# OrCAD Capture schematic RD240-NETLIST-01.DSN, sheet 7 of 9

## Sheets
7 3: size A3
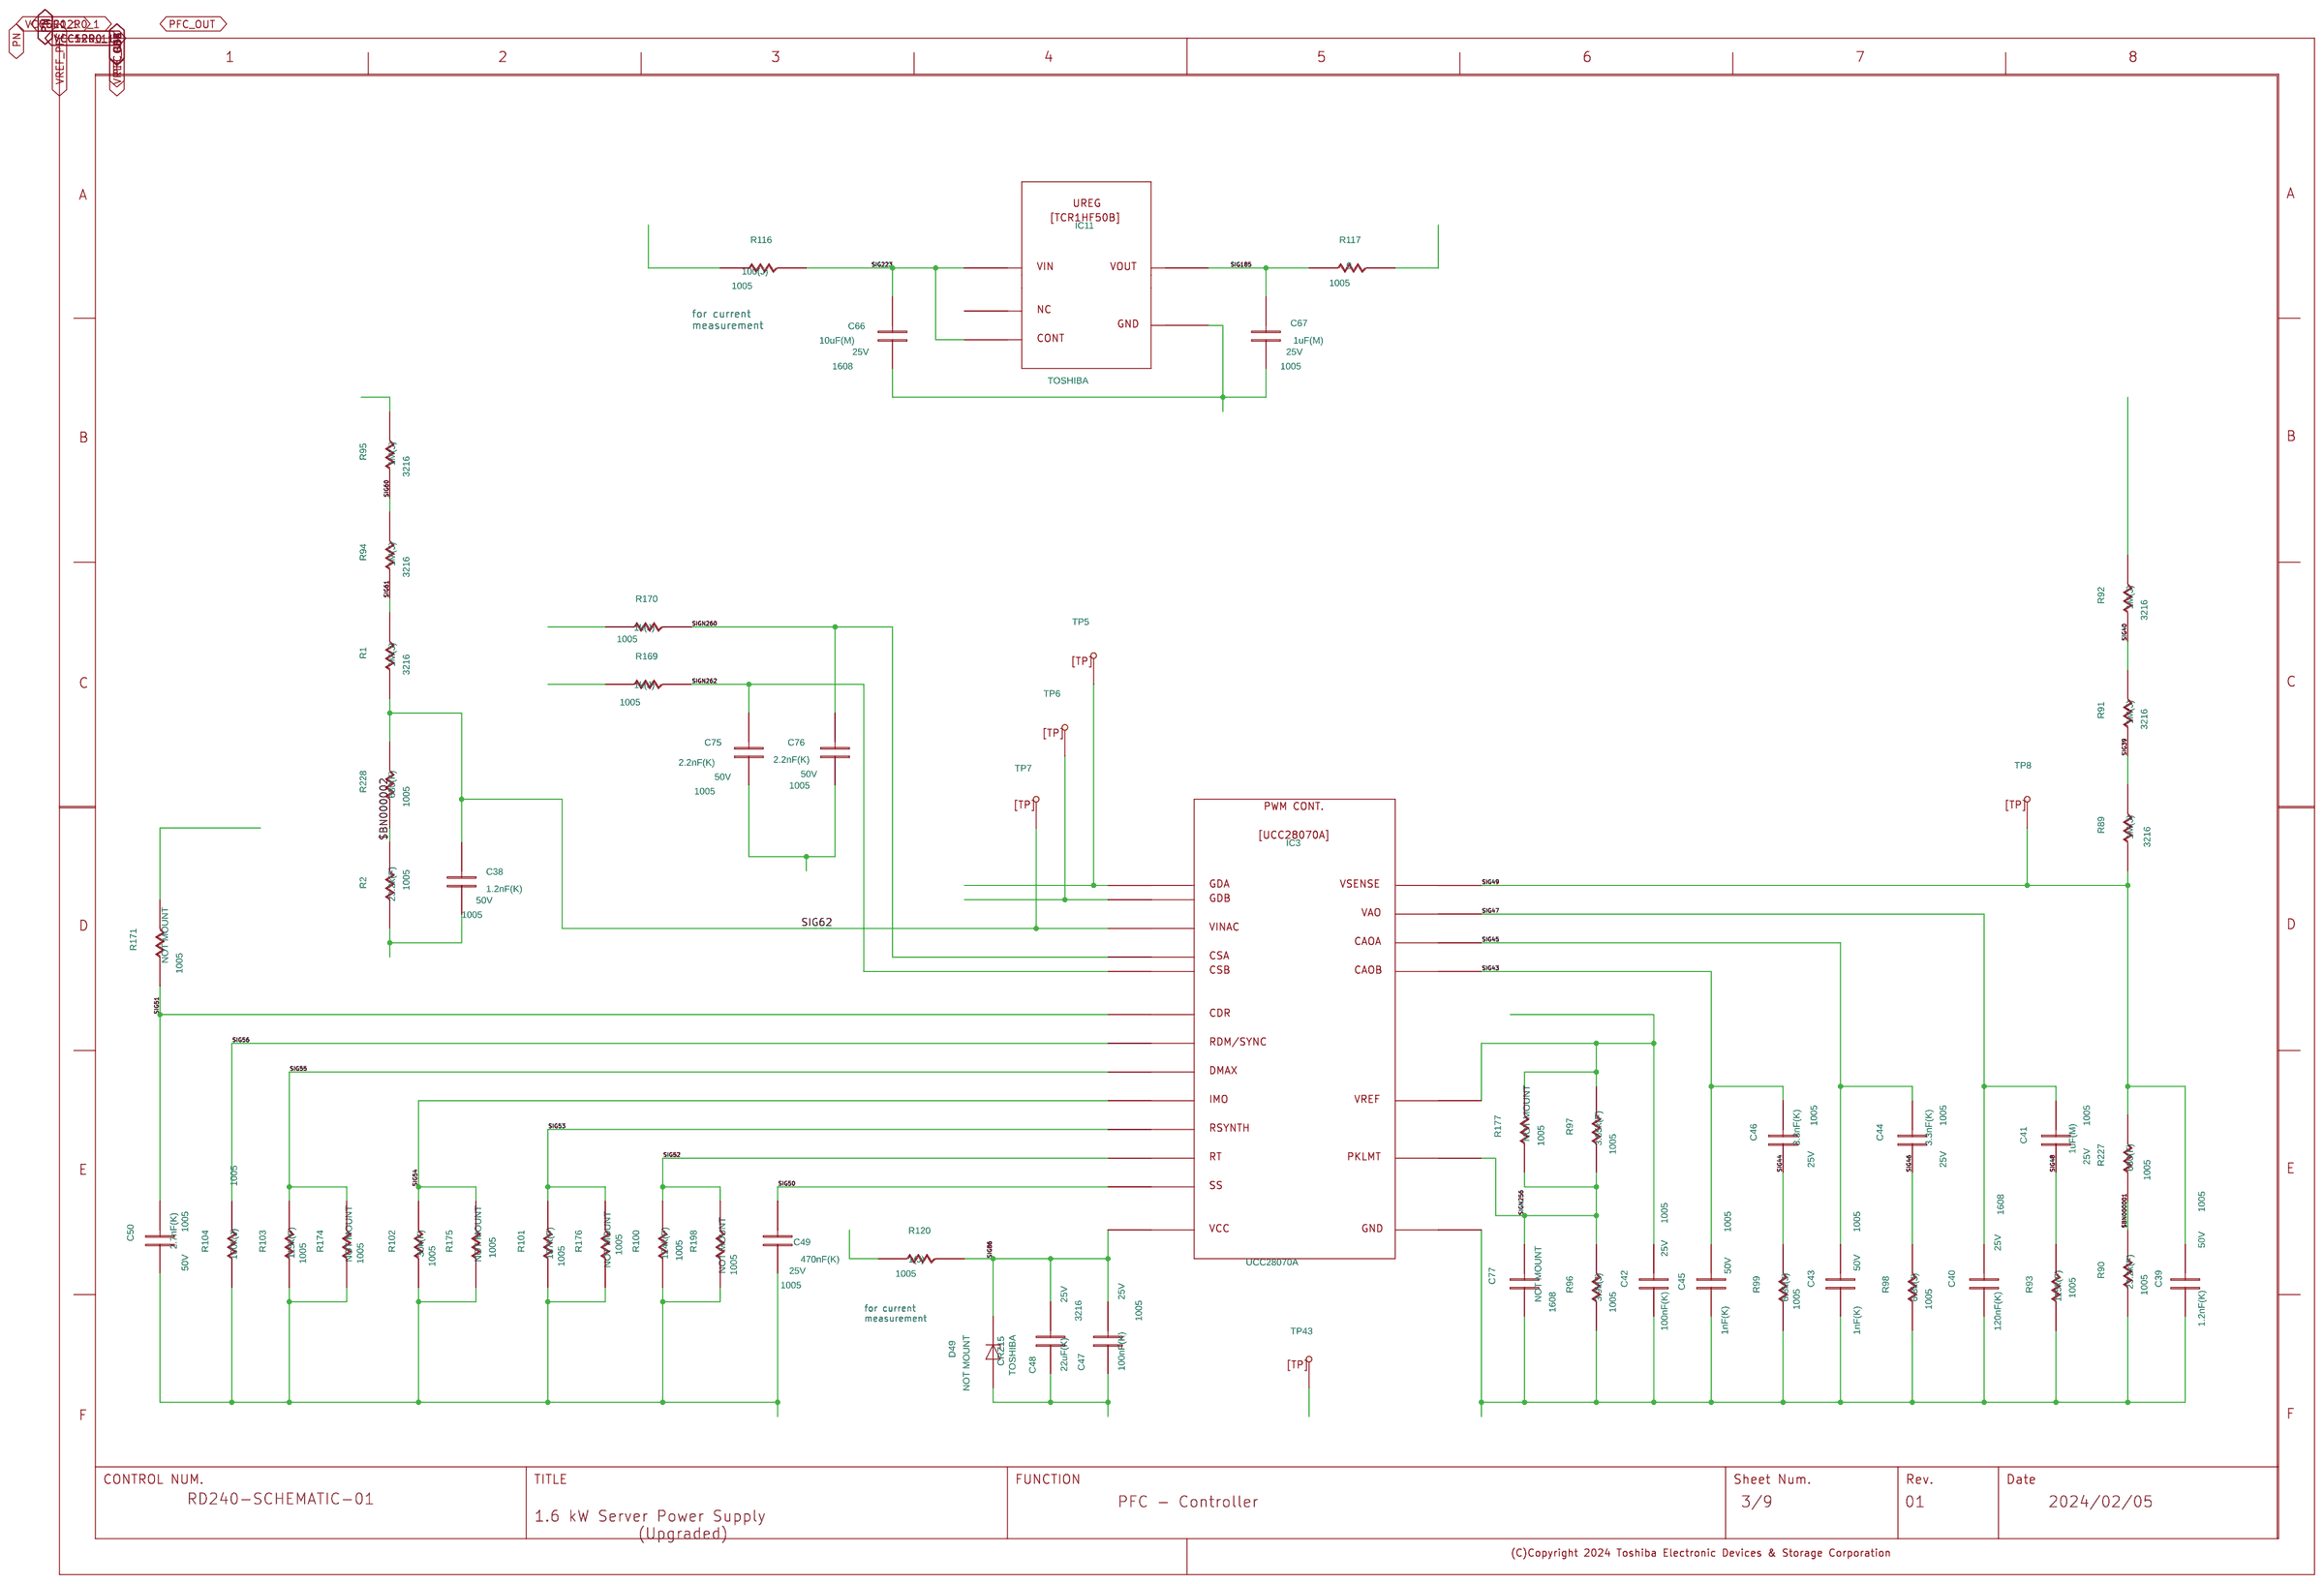
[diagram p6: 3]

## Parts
C38  C
C39  C
C40  C
C41  C
C42  C
C43  C
C44  C
C45  C
C46  C
C47  C
C48  C
C49  C
C50  C
C66  C
C67  C
C75  C
C76  C
C77  C
D49  ZD
IC3  L28070
IC11  TCR1HF50B
R1  R
R2  R
R89  R
R90  R
R91  R
R92  R
R93  R
R94  R
R95  R
R96  R
R97  R
R98  R
R99  R
R100  R
R101  R
R102  R
R103  R
R104  R
R116  R
R117  R
R120  R
R169  R
R170  R
R171  R
R174  R
R175  R
R176  R
R177  R
R198  R
R227  R
R228  R
TP5  TP
TP6  TP
TP7  TP
TP8  TP
TP43  TP
U?#6  WAKU_DEF100

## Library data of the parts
C38 = C: ADSMODELNAME: s_UMK105BJ122KV_F; AUTHOR: sptcae13; CAPACITANCETOLE: K; CDMASTERCADCELG: KC0005; CHIPSIZE: 1005; COMP: PRT_52; COMPONENTTYPE: 4; DATE: 2024/01/31; FNLEADFREETHET1GT2GMCTH1: 2_0_N; GCOUNT: 1; INSTANCENAME: cmp127; MAKER: TDK; MAXGCOUNT: 1; NOMINALCAPACITA: 1.2n; OUMECLASSIFICATION: ƒZƒ‰ƒ~ƒbƒNƒRƒ“ƒfƒ“ƒT; OUMEMAKER: TYD ‘¾—z—U“d; OUMEMAKERKATAMEI: UMK105BJ122KV-F; PMPRODUCTSTYPEG: HD1; QUADMODEL: CON_1.2N; RATEDVOLTAGE: 50; SAVECOUNT: 0; SIZECODESMD: 1005; TEMPCHARACTERI2: B; TIME: 13:58:26; UPDATEDATE: 2024/01/31; UPDATETIME: 13:58:26; UPDATEUSER: sptcae13; VAL1: 1.2nF(K); VAL2: 50V; VAL3: UMK105BJ122KV-F
C39 = C: ADSMODELNAME: s_UMK105BJ122KV_F; AUTHOR: sptcae13; CAPACITANCETOLE: K; CDMASTERCADCELG: KC0005; CHIPSIZE: 1005; COMP: PRT_52; COMPONENTTYPE: 4; DATE: 2024/01/31; FNLEADFREETHET1GT2GMCTH1: 2_0_N; GCOUNT: 1; INSTANCENAME: cmp128; MAKER: TDK; MAXGCOUNT: 1; NOMINALCAPACITA: 1.2n; OUMECLASSIFICATION: ƒZƒ‰ƒ~ƒbƒNƒRƒ“ƒfƒ“ƒT; OUMEMAKER: TYD ‘¾—z—U“d; OUMEMAKERKATAMEI: UMK105BJ122KV-F; PMPRODUCTSTYPEG: HD1; QUADMODEL: CON_1.2N; RATEDVOLTAGE: 50; SAVECOUNT: 0; SIZECODESMD: 1005; TEMPCHARACTERI2: B; TIME: 13:58:26; UPDATEDATE: 2024/01/31; UPDATETIME: 13:58:26; UPDATEUSER: sptcae13; VAL1: 1.2nF(K); VAL2: 50V; VAL3: UMK105BJ122KV-F
C40 = C: ADSMODELNAME: s_GCM188R71E154KA37D; AUTHOR: sptcae13; CAPACITANCETOLE: K; CDMASTERCADCELG: KC0008; CHIPSIZE: 1608; COMP: PRT_48; COMPONENTTYPE: 4; DATE: 2024/01/31; FNLEADFREETHET1GT2GMCTH1: N_N_N; GCOUNT: 1; INSTANCENAME: cmp76; MAKER: MURATA; MAXGCOUNT: 1; NOMINALCAPACITA: 150n; OUMECLASSIFICATION: ƒZƒ‰ƒ~ƒbƒNƒRƒ“ƒfƒ“ƒT; OUMEMAKER: MRT ºc»ì; OUMEMAKERKATAMEI: GCM188R71E154KA37D; PMPRODUCTSTYPEG: DME; QUADMODEL: CON_150N; RATEDVOLTAGE: 25; SAVECOUNT: 0; SIZECODESMD: 1608; TIME: 13:58:26; UPDATEDATE: 2024/01/31; UPDATETIME: 13:58:26; UPDATEUSER: sptcae13; VAL1: 120nF(K); VAL2: 25V; VAL3: GRM188R71E124KA01D
C41 = C: ADSMODELNAME: s_GCM31CR71H155KA55L; AUTHOR: sptcae13; CAPACITANCETOLE: K; CHIPSIZE: 2012; COMP: PRT_32; COMPONENTTYPE: 4; DATE: 2024/01/31; GCOUNT: 1; INSTANCENAME: cmp77; MAKER: TDK; MAXGCOUNT: 1; NOMINALCAPACITA: 1.5u; PMPRODUCTSTYPEG: DME; RATEDVOLTAGE: 50; SAVECOUNT: 0; SIZECODESMD: 1005; TIME: 13:58:26; UPDATEDATE: 2024/01/31; UPDATETIME: 13:58:26; UPDATEUSER: sptcae13; VAL1: 1uF(M); VAL2: 25V; VAL3: C1005X5R1E105M050BC
C42 = C: ADSMODELNAME: s_GRM155R71E104KE14D; AUTHOR: sptcae13; CAPACITANCETOLE: K; CDMASTERCADCELG: KC0005; CHIPSIZE: 1005; COMP: PRT_52; COMPONENTTYPE: 4; DATE: 2024/01/31; FNLEADFREETHET1GT2GMCTH1: N_N_N; GCOUNT: 1; INSTANCENAME: cmp62; MAKER: TDK; MAXGCOUNT: 1; NOMINALCAPACITA: 100n; OUMECLASSIFICATION: ƒZƒ‰ƒ~ƒbƒNƒRƒ“ƒfƒ“ƒT; OUMEMAKER: MRT ºc»ì; OUMEMAKERKATAMEI: GRM155R71E104KE14D; QUADMODEL: CON_100N; RATEDVOLTAGE: 25; SAVECOUNT: 0; SIZECODESMD: 1005; TIME: 13:58:26; UPDATEDATE: 2024/01/31; UPDATETIME: 13:58:26; UPDATEUSER: sptcae13; VAL1: 100nF(K); VAL2: 25V; VAL3: C1005X7R1E104K050BB
C43 = C: ADSMODELNAME: s_UMK105BJ102KV_F; AUTHOR: sptcae13; CAPACITANCETOLE: K; CDMASTERCADCELG: KC0005; CHIPSIZE: 1005; COMP: PRT_52; COMPONENTTYPE: 4; DATE: 2024/01/31; FNLEADFREETHET1GT2GMCTH1: 2_0_N; GCOUNT: 1; INSTANCENAME: cmp125; MAKER: TDK; MAXGCOUNT: 1; NOMINALCAPACITA: 1n; OUMECLASSIFICATION: ƒZƒ‰ƒ~ƒbƒNƒRƒ“ƒfƒ“ƒT; OUMEMAKER: TYD ‘¾—z—U“d; OUMEMAKERKATAMEI: UMK105BJ102KV-F; PMPRODUCTSTYPEG: HD1-PC1; QUADMODEL: CON_1N; RATEDVOLTAGE: 50; SAVECOUNT: 0; SIZECODESMD: 1005; TEMPCHARACTERI2: B; TIME: 13:58:26; UPDATEDATE: 2024/01/31; UPDATETIME: 13:58:26; UPDATEUSER: sptcae13; VAL1: 1nF(K); VAL2: 50V; VAL3: UMK105BJ102KV-F
C44 = C: ADSMODELNAME: s_C1005JB1E332KT; AUTHOR: sptcae13; CAPACITANCETOLE: K; CDMASTERCADCELG: KC0005; CHIPSIZE: 1005; COMP: PRT_52; COMPONENTTYPE: 4; DATE: 2024/01/31; FNLEADFREETHET1GT2GMCTH1: N_N_N; GCOUNT: 1; INSTANCENAME: cmp150; MAKER: TDK; MAXGCOUNT: 1; NOMINALCAPACITA: 3.3n; OUMECLASSIFICATION: ƒZƒ‰ƒ~ƒbƒNƒRƒ“ƒfƒ“ƒT; OUMEMAKER: TDK ‚s‚c‚j; OUMEMAKERKATAMEI: C1005JB1E332KT; QUADMODEL: CON_3.3N; RATEDVOLTAGE: 25; SAVECOUNT: 0; SIZECODESMD: 1005; TIME: 13:58:26; UPDATEDATE: 2024/01/31; UPDATETIME: 13:58:26; UPDATEUSER: sptcae13; VAL1: 3.3nF(K); VAL2: 25V; VAL3: CGJ2B2X7R1E332K050BA
C45 = C: ADSMODELNAME: s_UMK105BJ102KV_F; AUTHOR: sptcae13; CAPACITANCETOLE: K; CDMASTERCADCELG: KC0005; CHIPSIZE: 1005; COMP: PRT_52; COMPONENTTYPE: 4; DATE: 2024/01/31; FNLEADFREETHET1GT2GMCTH1: 2_0_N; GCOUNT: 1; INSTANCENAME: cmp126; MAKER: TDK; MAXGCOUNT: 1; NOMINALCAPACITA: 1n; OUMECLASSIFICATION: ƒZƒ‰ƒ~ƒbƒNƒRƒ“ƒfƒ“ƒT; OUMEMAKER: TYD ‘¾—z—U“d; OUMEMAKERKATAMEI: UMK105BJ102KV-F; PMPRODUCTSTYPEG: HD1-PC1; QUADMODEL: CON_1N; RATEDVOLTAGE: 50; SAVECOUNT: 0; SIZECODESMD: 1005; TEMPCHARACTERI2: B; TIME: 13:58:26; UPDATEDATE: 2024/01/31; UPDATETIME: 13:58:26; UPDATEUSER: sptcae13; VAL1: 1nF(K); VAL2: 50V; VAL3: UMK105BJ102KV-F
C46 = C: ADSMODELNAME: s_C1005JB1E332KT; AUTHOR: sptcae13; CAPACITANCETOLE: K; CDMASTERCADCELG: KC0005; CHIPSIZE: 1005; COMP: PRT_52; COMPONENTTYPE: 4; DATE: 2024/01/31; FNLEADFREETHET1GT2GMCTH1: N_N_N; GCOUNT: 1; INSTANCENAME: cmp149; MAKER: TDK; MAXGCOUNT: 1; NOMINALCAPACITA: 3.3n; OUMECLASSIFICATION: ƒZƒ‰ƒ~ƒbƒNƒRƒ“ƒfƒ“ƒT; OUMEMAKER: TDK ‚s‚c‚j; OUMEMAKERKATAMEI: C1005JB1E332KT; QUADMODEL: CON_3.3N; RATEDVOLTAGE: 25; SAVECOUNT: 0; SIZECODESMD: 1005; TIME: 13:58:26; UPDATEDATE: 2024/01/31; UPDATETIME: 13:58:26; UPDATEUSER: sptcae13; VAL1: 3.3nF(K); VAL2: 25V; VAL3: CGJ2B2X7R1E332K050BA
C47 = C: ADSCNVFLAG: ON; ADSCOMPONENTNAME: C_1005; ADSMODELNAME: s_GRM155R71E104KE14D; AUTHOR: sptcae13; CAPACITANCETOLE: K; CDMASTERCADCELG: KC0005; CHIPSIZE: 1005; COMP: PRT_52; COMPONENTTYPE: 4; DATE: 2024/01/31; FNLEADFREETHET1GT2GMCTH1: N_N_N; GCOUNT: 1; ICX_PART_MODEL: CON_100N; INSTANCENAME: cmp61; MAKER: TDK; MAXGCOUNT: 1; NOMINALCAPACITA: 100n; OUMECLASSIFICATION: ƒZƒ‰ƒ~ƒbƒNƒRƒ“ƒfƒ“ƒT; OUMEMAKER: MRT ºc»ì; OUMEMAKERKATAMEI: GRM155R71E104KE14D; QUADMODEL: CON_100N; RATEDVOLTAGE: 25; SAVECOUNT: 0; SIZECODESMD: 1005; SQ_PART_MODEL: CON_100N; TIME: 13:58:26; UPDATEDATE: 2024/01/31; UPDATETIME: 13:58:26; UPDATEUSER: sptcae13; VAL1: 100nF(K); VAL2: 25V; VAL3: C1005X7R1E104K050BB
C48 = C: ADSMODELNAME: s_GRM31CB31E226ME15D; AUTHOR: sptcae13; CAPACITANCETOLE: M; CDMASTERCADCELG: KC0014; CHIPSIZE: 3216; COMP: PRT_51; COMPONENTTYPE: 4; DATE: 2024/01/31; FNLEADFREETHET1GT2GMCTH1: N_N_N; GCOUNT: 1; INSTANCENAME: cmp147; MAKER: MURATA; MAXGCOUNT: 1; NOMINALCAPACITA: 22u; OUMECLASSIFICATION: ƒZƒ‰ƒ~ƒbƒNƒRƒ“ƒfƒ“ƒT; OUMEMAKER: MRT ºc»ì; OUMEMAKERKATAMEI: GRM31CB31E226ME15D; QUADMODEL: CON_22U; RATEDVOLTAGE: 25; SAVECOUNT: 0; SIZECODESMD: 3216; TEMPCHARACTERI2: B; TIME: 13:58:26; UPDATEDATE: 2024/01/31; UPDATETIME: 13:58:26; UPDATEUSER: sptcae13; VAL1: 22uF(K); VAL2: 25V; VAL3: GRM31CR61E226KE15L
C49 = C: ADSMODELNAME: s_GRM155R71E104KE14D; AUTHOR: sptcae13; CAPACITANCETOLE: K; CDMASTERCADCELG: KC0005; CHIPSIZE: 1005; COMP: PRT_52; COMPONENTTYPE: 4; DATE: 2024/01/31; FNLEADFREETHET1GT2GMCTH1: N_N_N; GCOUNT: 1; INSTANCENAME: cmp60; MAKER: TDK; MAXGCOUNT: 1; NOMINALCAPACITA: 100n; OUMECLASSIFICATION: ƒZƒ‰ƒ~ƒbƒNƒRƒ“ƒfƒ“ƒT; OUMEMAKER: MRT ºc»ì; OUMEMAKERKATAMEI: GRM155R71E104KE14D; QUADMODEL: CON_100N; RATEDVOLTAGE: 25; SAVECOUNT: 0; SIZECODESMD: 1005; TIME: 13:58:26; UPDATEDATE: 2024/01/31; UPDATETIME: 13:58:26; UPDATEUSER: sptcae13; VAL1: 470nF(K); VAL2: 25V; VAL3: C1005X5R1E474K050BB
C50 = C: ADSMODELNAME: s_UMK105BJ272KV_F; AUTHOR: sptcae13; CAPACITANCETOLE: K; CDMASTERCADCELG: DC834K; CHIPSIZE: 1005; COMP: PRT_52; COMPONENTTYPE: 4; DATE: 2024/01/31; FNLEADFREETHET1GT2GMCTH1: 3_0_N; GCOUNT: 1; INSTANCENAME: cmp131; MAKER: TDK; MAXGCOUNT: 1; NOMINALCAPACITA: 2.7n; OUMECLASSIFICATION: ƒZƒ‰ƒ~ƒbƒNƒRƒ“ƒfƒ“ƒT; OUMEMAKER: TYD ‘¾—z—U“d; OUMEMAKERKATAMEI: UMK105BJ272KV-F; PMPRODUCTSTYPEG: PC1; QUADMODEL: CON_2.7N; RATEDVOLTAGE: 50; SAVECOUNT: 0; SIZECODESMD: 1005; TEMPCHARACTERI2: B; TIME: 13:58:26; UPDATEDATE: 2024/01/31; UPDATETIME: 13:58:26; UPDATEUSER: sptcae13; VAL1: 2.7nF(K); VAL2: 50V; VAL3: UMK105BJ272KV-F
C66 = C: ADSMODELNAME: s_ZRB18AR61E106ME01L; AUTHOR: sptcae13; CAPACITANCETOLE: M; CDMASTERCADCELG: KC0167; CHIPSIZE: 1608; COMP: PRT_48; COMPONENTTYPE: 4; DATE: 2024/01/31; FNLEADFREETHET1GT2GMCTH1: N_N_N; GCOUNT: 1; INSTANCENAME: cmp160; MAKER: TDK; MAXGCOUNT: 1; NOMINALCAPACITA: 10u; OUMECLASSIFICATION: ƒZƒ‰ƒ~ƒbƒNƒRƒ“ƒfƒ“ƒT; OUMEMAKER: MRT ºc»ì; OUMEMAKERKATAMEI: ZRB18AR61E106ME01L; QUADMODEL: CON_10U; RATEDVOLTAGE: 25; SAVECOUNT: 0; SIZECODESMD: 1608; TIME: 13:58:26; UPDATEDATE: 2024/01/31; UPDATETIME: 13:58:26; UPDATEUSER: sptcae13; VAL1: 10uF(M); VAL2: 25V; VAL3: C1608X5R1E106M080AC
C67 = C: ADSCNVFLAG: ON; ADSCOMPONENTNAME: C_1608; ADSMODELNAME: s_GRM185B31E105KA12D; AUTHOR: sptcae13; CAPACITANCETOLE: K; CDMASTERCADCELG: KC0008; CHIPSIZE: 1005; COMP: PRT_52; COMPONENTTYPE: 4; DATE: 2024/01/31; FNLEADFREETHET1GT2GMCTH1: N_N_N; GCOUNT: 1; ICX_PART_MODEL: CON_1U; INSTANCENAME: cmp162; MAKER: TDK; MAXGCOUNT: 1; NOMINALCAPACITA: 1u; OUMECLASSIFICATION: ƒZƒ‰ƒ~ƒbƒNƒRƒ“ƒfƒ“ƒT; OUMEMAKER: MRT ºc»ì; OUMEMAKERKATAMEI: GRM185B31E105KA12D; PMPRODUCTSTYPEG: HD1; QUADMODEL: CON_1U; RATEDVOLTAGE: 25; SAVECOUNT: 0; SIZECODESMD: 1005; SQ_PART_MODEL: CON_1U; TEMPCHARACTERI2: B; TIME: 13:58:26; UPDATEDATE: 2024/01/31; UPDATETIME: 13:58:26; UPDATEUSER: sptcae13; VAL1: 1uF(M); VAL2: 25V; VAL3: C1005X5R1E105M050BC
C75 = C: ADSMODELNAME: s_UMK105BJ222KV_F; AUTHOR: sptcae13; CAPACITANCETOLE: K; CDMASTERCADCELG: KC0005; CHIPSIZE: 1005; COMP: PRT_52; COMPONENTTYPE: 4; DATE: 2024/01/31; FNLEADFREETHET1GT2GMCTH1: 2_0_N; GCOUNT: 1; INSTANCENAME: cmp129; MAKER: TDK; MAXGCOUNT: 1; NOMINALCAPACITA: 2.2n; OUMECLASSIFICATION: ƒZƒ‰ƒ~ƒbƒNƒRƒ“ƒfƒ“ƒT; OUMEMAKER: TYD ‘¾—z—U“d; OUMEMAKERKATAMEI: UMK105BJ222KV-F; PMPRODUCTSTYPEG: HD1-PC1; QUADMODEL: CON_2.2N; RATEDVOLTAGE: 50; SAVECOUNT: 0; SIZECODESMD: 1005; TEMPCHARACTERI2: B; TIME: 13:58:26; UPDATEDATE: 2024/01/31; UPDATETIME: 13:58:26; UPDATEUSER: sptcae13; VAL1: 2.2nF(K); VAL2: 50V; VAL3: UMK105BJ222KV-F
C76 = C: ADSMODELNAME: s_UMK105BJ222KV_F; AUTHOR: sptcae13; CAPACITANCETOLE: K; CDMASTERCADCELG: KC0005; CHIPSIZE: 1005; COMP: PRT_52; COMPONENTTYPE: 4; DATE: 2024/01/31; FNLEADFREETHET1GT2GMCTH1: 2_0_N; GCOUNT: 1; INSTANCENAME: cmp130; MAKER: TDK; MAXGCOUNT: 1; NOMINALCAPACITA: 2.2n; OLDCOMPONENTID: 99; OUMECLASSIFICATION: ƒZƒ‰ƒ~ƒbƒNƒRƒ“ƒfƒ“ƒT; OUMEMAKER: TYD ‘¾—z—U“d; OUMEMAKERKATAMEI: UMK105BJ222KV-F; PMPRODUCTSTYPEG: HD1-PC1; QUADMODEL: CON_2.2N; RATEDVOLTAGE: 50; SAVECOUNT: 0; SIZECODESMD: 1005; TEMPCHARACTERI2: B; TIME: 13:58:26; UPDATEDATE: 2024/01/31; UPDATETIME: 13:58:26; UPDATEUSER: sptcae13; VAL1: 2.2nF(K); VAL2: 50V; VAL3: UMK105BJ222KV-F
C77 = C: AUTHOR: sptcae13; CHIPSIZE: 1608; COMP: PRT_48; COMPONENTTYPE: 4; DATE: 2024/01/31; INSTANCENAME: cmp93; MAKER: MURATA; NOTMOUNT: NOT MOUNT; SAVECOUNT: 0; SIZECODESMD: 1608; TIME: 13:58:26; UPDATEDATE: 2024/01/31; UPDATETIME: 13:58:26; UPDATEUSER: sptcae13; VAL1: 100pF(J); VAL2: 50V; VAL3: GRM1885C1H101JA01D
D49 = ZD: ADSMODELNAME: s_CRZ15; CDMASTERCADCELG: MMK0167; COMPONENTTYPE: 4; FNLEADFREETHET1GT2GMCTH1: N_N_N; FORWARDVOLTAGEM: 0; GCOUNT: 1; INSTANCENAME: cmp51; MAXAVERAGEFORWA: 0; MAXGCOUNT: 1; MAXREPETITIVEPE: 0; MAXREVERSEVOLTA: 0; MOUNTINGFORMSMD: SMD; NOTMOUNT: NOT MOUNT; OUMECLASSIFICATION: èd³_CI[h; OUMEMAKER: TSB “ŒŽÅ; OUMEMAKERKATAMEI: CRZ15; OUMEPARTTYPE: D; PEAKFORWARDVOLT: 0; REVERSECURRENT: 0; USERCOMPTEXT3: TOSHIBA; VAL3: CRZ15; ZENERVOLTAGEMAX: 16.5; ZENERVOLTAGEMIN: 13.5
IC3 = L28070: COMP: PRT_59; COMPONENTTYPE: 4; INSTANCENAME: cmp10; MAKER: TEXAS; VAL3: UCC28070A
IC11 = TCR1HF50B: COMPONENTTYPE: 4; INSTANCENAME: cmp172; USERCOMPTEXT3: TOSHIBA
R1 = R: ADSMODELNAME: s_RK73H1JTTD1004F; CDMASTERCADCELG: KC0167; CHIPSIZE: 1608; COMPONENTTYPE: 4; FNLEADFREETHET1GT2GMCTH1: N_N_N; GCOUNT: 1; INSTANCENAME: cmp137; MAKER: KOA; MAXGCOUNT: 1; MOUNTINGFORMSMD: SMD; NOMINALRESISTAN: 1M; OUMECLASSIFICATION: \ÊÀpÅèïRí; OUMEMAKER: KOA R[A; OUMEMAKERKATAMEI: RK73H1JTTD1004F; POWERRATING: 100m; QUADMODEL: RES_1M; RESISTANCETOLER: F; SAVECOUNT: 0; SIZECODESMD: 3216; VAL1: 1M(J); VAL2: 250mW; VAL3: RK73B2BTTD105J
R2 = R: ADSMODELNAME: s_RC0402FR_071KL; ALLGREEN: 0:O[; CDMASTERCADCELG: KC0005; CHIPSIZE: 1608; COMPONENTTYPE: 4; FNAPPROVALRESUG: B:i(GREEN); FNCANCELLATIONG: 0:Žg—p‰Â; FNENVIRONMANTRG: 1:gpL(K§ÎÛO); FNLEADFREETHET1GT2GMCTH1: 2_2_N; GANSWERREV: 8; GCOUNT: 1; INSTANCENAME: cmp138; MAKER: PANASONIC; MAXGCOUNT: 1; MOUNTINGFORMSMD: SMD; NOMINALRESISTAN: 1K; OUMECLASSIFICATION: \ÊÀpÅèïRí; OUMEMAKER: YGO ƒ„ƒQƒI; OUMEMAKERKATAMEI: RC0402FR-071KL; PMPRODUCTSTYPEG: HD1; POWERRATING: 63m; QUADMODEL: RES_1K; RESISTANCETOLER: F; SAVECOUNT: 0; SIZECODESMD: 1005; VAL1: 23.2k(F); VAL2: 63mW; VAL3: ERJ2RKF2322X
R89 = R: ADSMODELNAME: s_RK73H1JTTD1004F; CDMASTERCADCELG: KC0167; CHIPSIZE: 1608; COMPONENTTYPE: 4; FNLEADFREETHET1GT2GMCTH1: N_N_N; GCOUNT: 1; INSTANCENAME: cmp142; MAKER: KOA; MAXGCOUNT: 1; MOUNTINGFORMSMD: SMD; NOMINALRESISTAN: 1M; OUMECLASSIFICATION: \ÊÀpÅèïRí; OUMEMAKER: KOA R[A; OUMEMAKERKATAMEI: RK73H1JTTD1004F; POWERRATING: 100m; QUADMODEL: RES_1M; RESISTANCETOLER: F; SAVECOUNT: 0; SIZECODESMD: 3216; VAL1: 1M(J); VAL2: 250mW; VAL3: RK73B2BTTD105J
R90 = R: ADSMODELNAME: s_RC0402FR_071KL; ALLGREEN: 0:O[; CDMASTERCADCELG: KC0005; CHIPSIZE: 1608; COMPONENTTYPE: 4; FNAPPROVALRESUG: B:i(GREEN); FNCANCELLATIONG: 0:Žg—p‰Â; FNENVIRONMANTRG: 1:gpL(K§ÎÛO); FNLEADFREETHET1GT2GMCTH1: 2_2_N; GANSWERREV: 8; GCOUNT: 1; INSTANCENAME: cmp153; MAKER: PANASONIC; MAXGCOUNT: 1; MOUNTINGFORMSMD: SMD; NOMINALRESISTAN: 1K; OUMECLASSIFICATION: \ÊÀpÅèïRí; OUMEMAKER: YGO ƒ„ƒQƒI; OUMEMAKERKATAMEI: RC0402FR-071KL; PMPRODUCTSTYPEG: HD1; POWERRATING: 63m; QUADMODEL: RES_1K; RESISTANCETOLER: F; SAVECOUNT: 0; SIZECODESMD: 1005; VAL1: 23.2k(F); VAL2: 63mW; VAL3: ERJ2RKF2322X
R91 = R: ADSMODELNAME: s_RK73H1JTTD1004F; CDMASTERCADCELG: KC0167; CHIPSIZE: 1608; COMPONENTTYPE: 4; FNLEADFREETHET1GT2GMCTH1: N_N_N; GCOUNT: 1; INSTANCENAME: cmp141; MAKER: KOA; MAXGCOUNT: 1; MOUNTINGFORMSMD: SMD; NOMINALRESISTAN: 1M; OUMECLASSIFICATION: \ÊÀpÅèïRí; OUMEMAKER: KOA R[A; OUMEMAKERKATAMEI: RK73H1JTTD1004F; POWERRATING: 100m; QUADMODEL: RES_1M; RESISTANCETOLER: F; SAVECOUNT: 0; SIZECODESMD: 3216; VAL1: 1M(J); VAL2: 250mW; VAL3: RK73B2BTTD105J
R92 = R: ADSMODELNAME: s_RK73H1JTTD1004F; CDMASTERCADCELG: KC0167; CHIPSIZE: 1608; COMPONENTTYPE: 4; FNLEADFREETHET1GT2GMCTH1: N_N_N; GCOUNT: 1; INSTANCENAME: cmp143; MAKER: KOA; MAXGCOUNT: 1; MOUNTINGFORMSMD: SMD; NOMINALRESISTAN: 1M; OUMECLASSIFICATION: \ÊÀpÅèïRí; OUMEMAKER: KOA R[A; OUMEMAKERKATAMEI: RK73H1JTTD1004F; POWERRATING: 100m; QUADMODEL: RES_1M; RESISTANCETOLER: F; SAVECOUNT: 0; SIZECODESMD: 3216; VAL1: 1M(J); VAL2: 250mW; VAL3: RK73B2BTTD105J
R93 = R: ADSMODELNAME: s_RC0402FR_071KL; ALLGREEN: 0:O[; CDMASTERCADCELG: KC0005; CHIPSIZE: 1608; COMPONENTTYPE: 4; FNAPPROVALRESUG: B:i(GREEN); FNCANCELLATIONG: 0:Žg—p‰Â; FNENVIRONMANTRG: 1:gpL(K§ÎÛO); FNLEADFREETHET1GT2GMCTH1: 2_2_N; GANSWERREV: 8; GCOUNT: 1; INSTANCENAME: cmp152; MAKER: PANASONIC; MAXGCOUNT: 1; MOUNTINGFORMSMD: SMD; NOMINALRESISTAN: 1K; OUMECLASSIFICATION: \ÊÀpÅèïRí; OUMEMAKER: YGO ƒ„ƒQƒI; OUMEMAKERKATAMEI: RC0402FR-071KL; PMPRODUCTSTYPEG: HD1; POWERRATING: 63m; QUADMODEL: RES_1K; RESISTANCETOLER: F; SAVECOUNT: 0; SIZECODESMD: 1005; VAL1: 115k(F); VAL2: 63mW; VAL3: ERJ2RKF1153X
R94 = R: ADSMODELNAME: s_RK73H1JTTD1004F; CDMASTERCADCELG: KC0167; CHIPSIZE: 1608; COMPONENTTYPE: 4; FNLEADFREETHET1GT2GMCTH1: N_N_N; GCOUNT: 1; INSTANCENAME: cmp135; MAKER: KOA; MAXGCOUNT: 1; MOUNTINGFORMSMD: SMD; NOMINALRESISTAN: 1M; OUMECLASSIFICATION: \ÊÀpÅèïRí; OUMEMAKER: KOA R[A; OUMEMAKERKATAMEI: RK73H1JTTD1004F; POWERRATING: 100m; QUADMODEL: RES_1M; RESISTANCETOLER: F; SAVECOUNT: 0; SIZECODESMD: 3216; VAL1: 1M(J); VAL2: 250mW; VAL3: RK73B2BTTD105J
R95 = R: ADSMODELNAME: s_RK73H1JTTD1004F; CDMASTERCADCELG: KC0167; CHIPSIZE: 1608; COMPONENTTYPE: 4; FNLEADFREETHET1GT2GMCTH1: N_N_N; GCOUNT: 1; INSTANCENAME: cmp136; MAKER: KOA; MAXGCOUNT: 1; MOUNTINGFORMSMD: SMD; NOMINALRESISTAN: 1M; OUMECLASSIFICATION: \ÊÀpÅèïRí; OUMEMAKER: KOA R[A; OUMEMAKERKATAMEI: RK73H1JTTD1004F; POWERRATING: 100m; QUADMODEL: RES_1M; RESISTANCETOLER: F; SAVECOUNT: 0; SIZECODESMD: 3216; VAL1: 1M(J); VAL2: 250mW; VAL3: RK73B2BTTD105J
R96 = R: ADSMODELNAME: s_RC0402FR_071KL; ALLGREEN: 0:O[; CDMASTERCADCELG: KC0005; CHIPSIZE: 1608; COMPONENTTYPE: 4; FNAPPROVALRESUG: B:i(GREEN); FNCANCELLATIONG: 0:Žg—p‰Â; FNENVIRONMANTRG: 1:gpL(K§ÎÛO); FNLEADFREETHET1GT2GMCTH1: 2_2_N; GANSWERREV: 8; GCOUNT: 1; INSTANCENAME: cmp97; MAKER: KOA; MAXGCOUNT: 1; MOUNTINGFORMSMD: SMD; NOMINALRESISTAN: 1K; OUMECLASSIFICATION: \ÊÀpÅèïRí; OUMEMAKER: YGO ƒ„ƒQƒI; OUMEMAKERKATAMEI: RC0402FR-071KL; PMPRODUCTSTYPEG: HD1; POWERRATING: 63m; QUADMODEL: RES_1K; RESISTANCETOLER: F; SAVECOUNT: 0; SIZECODESMD: 1005; VAL1: 3.9k(J); VAL2: 63mW; VAL3: RK73B1ETTP392J
R97 = R: ADSMODELNAME: s_RC0402FR_071KL; ALLGREEN: 0:O[; CDMASTERCADCELG: KC0005; CHIPSIZE: 1608; COMPONENTTYPE: 4; FNAPPROVALRESUG: B:i(GREEN); FNCANCELLATIONG: 0:Žg—p‰Â; FNENVIRONMANTRG: 1:gpL(K§ÎÛO); FNLEADFREETHET1GT2GMCTH1: 2_2_N; GANSWERREV: 8; GCOUNT: 1; INSTANCENAME: cmp96; MAKER: PANASONIC; MAXGCOUNT: 1; MOUNTINGFORMSMD: SMD; NOMINALRESISTAN: 1K; OUMECLASSIFICATION: \ÊÀpÅèïRí; OUMEMAKER: YGO ƒ„ƒQƒI; OUMEMAKERKATAMEI: RC0402FR-071KL; PMPRODUCTSTYPEG: HD1; POWERRATING: 63m; QUADMODEL: RES_1K; RESISTANCETOLER: F; SAVECOUNT: 0; SIZECODESMD: 1005; VAL1: 3.65k(F); VAL2: 63mW; VAL3: ERJ2RKF3651X
R98 = R: ADSMODELNAME: s_RC0402FR_071KL; ALLGREEN: 0:O[; CDMASTERCADCELG: KC0005; CHIPSIZE: 1608; COMPONENTTYPE: 4; FNAPPROVALRESUG: B:i(GREEN); FNCANCELLATIONG: 0:Žg—p‰Â; FNENVIRONMANTRG: 1:gpL(K§ÎÛO); FNLEADFREETHET1GT2GMCTH1: 2_2_N; GANSWERREV: 8; GCOUNT: 1; INSTANCENAME: cmp151; MAKER: KOA; MAXGCOUNT: 1; MOUNTINGFORMSMD: SMD; NOMINALRESISTAN: 1K; OUMECLASSIFICATION: \ÊÀpÅèïRí; OUMEMAKER: YGO ƒ„ƒQƒI; OUMEMAKERKATAMEI: RC0402FR-071KL; PMPRODUCTSTYPEG: HD1; POWERRATING: 63m; QUADMODEL: RES_1K; RESISTANCETOLER: F; SAVECOUNT: 0; SIZECODESMD: 1005; VAL1: 6.8k(J); VAL2: 63mW; VAL3: RK73B1ETTP682J
R99 = R: ADSMODELNAME: s_RC0402FR_071KL; ALLGREEN: 0:O[; CDMASTERCADCELG: KC0005; CHIPSIZE: 1608; COMPONENTTYPE: 4; FNAPPROVALRESUG: B:i(GREEN); FNCANCELLATIONG: 0:Žg—p‰Â; FNENVIRONMANTRG: 1:gpL(K§ÎÛO); FNLEADFREETHET1GT2GMCTH1: 2_2_N; GANSWERREV: 8; GCOUNT: 1; INSTANCENAME: cmp148; MAKER: KOA; MAXGCOUNT: 1; MOUNTINGFORMSMD: SMD; NOMINALRESISTAN: 1K; OUMECLASSIFICATION: \ÊÀpÅèïRí; OUMEMAKER: YGO ƒ„ƒQƒI; OUMEMAKERKATAMEI: RC0402FR-071KL; PMPRODUCTSTYPEG: HD1; POWERRATING: 63m; QUADMODEL: RES_1K; RESISTANCETOLER: F; SAVECOUNT: 0; SIZECODESMD: 1005; VAL1: 6.8k(J); VAL2: 63mW; VAL3: RK73B1ETTP682J
R100 = R: ADSMODELNAME: s_RC0402FR_071KL; ALLGREEN: 0:O[; CDMASTERCADCELG: KC0005; CHIPSIZE: 1608; COMPONENTTYPE: 4; FNAPPROVALRESUG: B:i(GREEN); FNCANCELLATIONG: 0:Žg—p‰Â; FNENVIRONMANTRG: 1:gpL(K§ÎÛO); FNLEADFREETHET1GT2GMCTH1: 2_2_N; GANSWERREV: 8; GCOUNT: 1; INSTANCENAME: cmp146; MAKER: PANASONIC; MAXGCOUNT: 1; MOUNTINGFORMSMD: SMD; NOMINALRESISTAN: 1K; OUMECLASSIFICATION: \ÊÀpÅèïRí; OUMEMAKER: YGO ƒ„ƒQƒI; OUMEMAKERKATAMEI: RC0402FR-071KL; PMPRODUCTSTYPEG: HD1; POWERRATING: 63m; QUADMODEL: RES_1K; RESISTANCETOLER: F; SAVECOUNT: 0; SIZECODESMD: 1005; VAL1: 124k(F); VAL2: 63mW; VAL3: ERJ2RKF1243X
R101 = R: ADSMODELNAME: s_RC0402FR_071KL; ALLGREEN: 0:O[; CDMASTERCADCELG: KC0005; CHIPSIZE: 1608; COMPONENTTYPE: 4; FNAPPROVALRESUG: B:i(GREEN); FNCANCELLATIONG: 0:Žg—p‰Â; FNENVIRONMANTRG: 1:gpL(K§ÎÛO); FNLEADFREETHET1GT2GMCTH1: 2_2_N; GANSWERREV: 8; GCOUNT: 1; INSTANCENAME: cmp98; MAKER: PANASONIC; MAXGCOUNT: 1; MOUNTINGFORMSMD: SMD; NOMINALRESISTAN: 1K; OUMECLASSIFICATION: \ÊÀpÅèïRí; OUMEMAKER: YGO ƒ„ƒQƒI; OUMEMAKERKATAMEI: RC0402FR-071KL; PMPRODUCTSTYPEG: HD1; POWERRATING: 63m; QUADMODEL: RES_1K; RESISTANCETOLER: F; SAVECOUNT: 0; SIZECODESMD: 1005; VAL1: 187k(F); VAL2: 63mW; VAL3: ERJ2RKF1873X
R102 = R: ADSMODELNAME: s_RC0402FR_071KL; ALLGREEN: 0:O[; CDMASTERCADCELG: KC0005; CHIPSIZE: 1608; COMPONENTTYPE: 4; FNAPPROVALRESUG: B:i(GREEN); FNCANCELLATIONG: 0:Žg—p‰Â; FNENVIRONMANTRG: 1:gpL(K§ÎÛO); FNLEADFREETHET1GT2GMCTH1: 2_2_N; GANSWERREV: 8; GCOUNT: 1; INSTANCENAME: cmp145; MAKER: KOA; MAXGCOUNT: 1; MOUNTINGFORMSMD: SMD; NOMINALRESISTAN: 1K; OUMECLASSIFICATION: \ÊÀpÅèïRí; OUMEMAKER: YGO ƒ„ƒQƒI; OUMEMAKERKATAMEI: RC0402FR-071KL; PMPRODUCTSTYPEG: HD1; POWERRATING: 63m; QUADMODEL: RES_1K; RESISTANCETOLER: F; SAVECOUNT: 0; SIZECODESMD: 1005; VAL1: 30k(F); VAL2: 63mW; VAL3: ERJ2RKF3002X
R103 = R: ADSMODELNAME: s_RC0402FR_071KL; ALLGREEN: 0:O[; CDMASTERCADCELG: KC0005; CHIPSIZE: 1608; COMPONENTTYPE: 4; FNAPPROVALRESUG: B:i(GREEN); FNCANCELLATIONG: 0:Žg—p‰Â; FNENVIRONMANTRG: 1:gpL(K§ÎÛO); FNLEADFREETHET1GT2GMCTH1: 2_2_N; GANSWERREV: 8; GCOUNT: 1; INSTANCENAME: cmp95; MAKER: PANASONIC; MAXGCOUNT: 1; MOUNTINGFORMSMD: SMD; NOMINALRESISTAN: 1K; OUMECLASSIFICATION: \ÊÀpÅèïRí; OUMEMAKER: YGO ƒ„ƒQƒI; OUMEMAKERKATAMEI: RC0402FR-071KL; PMPRODUCTSTYPEG: HD1; POWERRATING: 63m; QUADMODEL: RES_1K; RESISTANCETOLER: F; SAVECOUNT: 0; SIZECODESMD: 1005; VAL1: 115k(F); VAL2: 63mW; VAL3: ERJ2RKF1153X
R104 = R: ADSMODELNAME: s_RC0402FR_071KL; ALLGREEN: 0:O[; CDMASTERCADCELG: KC0005; CHIPSIZE: 1608; COMPONENTTYPE: 4; FNAPPROVALRESUG: B:i(GREEN); FNCANCELLATIONG: 0:Žg—p‰Â; FNENVIRONMANTRG: 1:gpL(K§ÎÛO); FNLEADFREETHET1GT2GMCTH1: 2_2_N; GANSWERREV: 8; GCOUNT: 1; INSTANCENAME: cmp144; MAKER: KOA; MAXGCOUNT: 1; MOUNTINGFORMSMD: SMD; NOMINALRESISTAN: 1K; OUMECLASSIFICATION: \ÊÀpÅèïRí; OUMEMAKER: YGO ƒ„ƒQƒI; OUMEMAKERKATAMEI: RC0402FR-071KL; PMPRODUCTSTYPEG: HD1; POWERRATING: 63m; QUADMODEL: RES_1K; RESISTANCETOLER: F; SAVECOUNT: 0; SIZECODESMD: 1005; VAL1: 100k(J); VAL2: 63mW; VAL3: RK73B1ETTP104J
R116 = R: ADSMODELNAME: s_RC0402FR_071KL; ALLGREEN: 0:O[; CDMASTERCADCELG: KC0005; CHIPSIZE: 1608; COMPONENTTYPE: 4; FNAPPROVALRESUG: B:i(GREEN); FNCANCELLATIONG: 0:Žg—p‰Â; FNENVIRONMANTRG: 1:gpL(K§ÎÛO); FNLEADFREETHET1GT2GMCTH1: 2_2_N; GANSWERREV: 8; GCOUNT: 1; INSTANCENAME: cmp163; MAKER: KOA; MAXGCOUNT: 1; MOUNTINGFORMSMD: SMD; NOMINALRESISTAN: 1K; OUMECLASSIFICATION: \ÊÀpÅèïRí; OUMEMAKER: YGO ƒ„ƒQƒI; OUMEMAKERKATAMEI: RC0402FR-071KL; PMPRODUCTSTYPEG: HD1; POWERRATING: 63m; QUADMODEL: RES_1K; RESISTANCETOLER: F; SAVEAREA0: -588,-4192,15498,7584; SAVECOUNT: 0; SIZECODESMD: 1005; UPDATETIME: 09:21:07; VAL1: 100(J); VAL2: 63mW; VAL3: RK73K1ETP101J
R117 = R: ADSCNVFLAG: ON; ADSCOMPONENTNAME: R_1005; ADSMODELNAME: s_RC0402FR_071KL; ALLGREEN: 0:O[; CDMASTERCADCELG: KC0005; CHIPSIZE: 1608; COMPONENTTYPE: 4; FNAPPROVALRESUG: B:i(GREEN); FNCANCELLATIONG: 0:Žg—p‰Â; FNENVIRONMANTRG: 1:gpL(K§ÎÛO); FNLEADFREETHET1GT2GMCTH1: 2_2_N; GANSWERREV: 8; GCOUNT: 1; ICX_PART_MODEL: RES_0; INSTANCENAME: cmp165; MAKER: KOA; MAXGCOUNT: 1; MOUNTINGFORMSMD: SMD; NOMINALRESISTAN: 1K; OUMECLASSIFICATION: \ÊÀpÅèïRí; OUMEMAKER: YGO ƒ„ƒQƒI; OUMEMAKERKATAMEI: RC0402FR-071KL; PMPRODUCTSTYPEG: HD1; POWERRATING: 63m; QUADMODEL: RES_1K; RESISTANCETOLER: F; SAVEAREA0: -588,-4192,15498,7584; SAVECOUNT: 0; SIZECODESMD: 1005; SQ_PART_MODEL: RES_0; UPDATETIME: 09:21:07; VAL1: 0; VAL2: 63mW; VAL3: RK73Z1ETTP
R120 = R: ADSMODELNAME: s_RC0402FR_071KL; ALLGREEN: 0:O[; CDMASTERCADCELG: KC0005; CHIPSIZE: 1608; COMPONENTTYPE: 4; FNAPPROVALRESUG: B:i(GREEN); FNCANCELLATIONG: 0:Žg—p‰Â; FNENVIRONMANTRG: 1:gpL(K§ÎÛO); FNLEADFREETHET1GT2GMCTH1: 2_2_N; GANSWERREV: 8; GCOUNT: 1; INSTANCENAME: cmp69; MAKER: PANASONIC; MAXGCOUNT: 1; MOUNTINGFORMSMD: SMD; NOMINALRESISTAN: 1K; OUMECLASSIFICATION: \ÊÀpÅèïRí; OUMEMAKER: YGO ƒ„ƒQƒI; OUMEMAKERKATAMEI: RC0402FR-071KL; PMPRODUCTSTYPEG: HD1; POWERRATING: 63m; QUADMODEL: RES_1K; RESISTANCETOLER: F; SAVECOUNT: 0; SIZECODESMD: 1005; VAL1: 1(J); VAL2: 63mW; VAL3: ERJ2GEJ1R0X
R169 = R: ADSMODELNAME: s_RC0402FR_071KL; ALLGREEN: 0:O[; CDMASTERCADCELG: KC0005; CHIPSIZE: 1608; COMPONENTTYPE: 4; FNAPPROVALRESUG: B:i(GREEN); FNCANCELLATIONG: 0:Žg—p‰Â; FNENVIRONMANTRG: 1:gpL(K§ÎÛO); FNLEADFREETHET1GT2GMCTH1: 2_2_N; GANSWERREV: 8; GCOUNT: 1; INSTANCENAME: cmp139; MAKER: KOA; MAXGCOUNT: 1; MOUNTINGFORMSMD: SMD; NOMINALRESISTAN: 1K; OUMECLASSIFICATION: \ÊÀpÅèïRí; OUMEMAKER: YGO ƒ„ƒQƒI; OUMEMAKERKATAMEI: RC0402FR-071KL; PMPRODUCTSTYPEG: HD1; POWERRATING: 63m; QUADMODEL: RES_1K; RESISTANCETOLER: F; SAVECOUNT: 0; SIZECODESMD: 1005; VAL1: 1k(J); VAL2: 63mW; VAL3: RK73K1ETP102J
R170 = R: ADSMODELNAME: s_RC0402FR_071KL; ALLGREEN: 0:O[; CDMASTERCADCELG: KC0005; CHIPSIZE: 1608; COMPONENTTYPE: 4; FNAPPROVALRESUG: B:i(GREEN); FNCANCELLATIONG: 0:Žg—p‰Â; FNENVIRONMANTRG: 1:gpL(K§ÎÛO); FNLEADFREETHET1GT2GMCTH1: 2_2_N; GANSWERREV: 8; GCOUNT: 1; INSTANCENAME: cmp140; MAKER: KOA; MAXGCOUNT: 1; MOUNTINGFORMSMD: SMD; NOMINALRESISTAN: 1K; OLDCOMPONENTID: 100; OUMECLASSIFICATION: \ÊÀpÅèïRí; OUMEMAKER: YGO ƒ„ƒQƒI; OUMEMAKERKATAMEI: RC0402FR-071KL; PMPRODUCTSTYPEG: HD1; POWERRATING: 63m; QUADMODEL: RES_1K; RESISTANCETOLER: F; SAVECOUNT: 0; SIZECODESMD: 1005; VAL1: 1k(J); VAL2: 63mW; VAL3: RK73K1ETP102J
R171 = R: ADSMODELNAME: s_RK73Z1JTTD; CDMASTERCADCELG: KCK0203; CHIPSIZE: 1608; COMP: GDM010004481; COMPONENTTYPE: 4; DATE: 2024/01/31; FNLEADFREETHET1GT2GMCTH1: 3_2_N; GCOUNT: 1; INSTANCENAME: cmp134; MAKER: KOA; MAXGCOUNT: 1; MOUNTINGFORMSMD: SMD; NOMINALRESISTAN: 0; NOTMOUNT: NOT MOUNT; OUMECLASSIFICATION: \ÊÀpÅèïRí; OUMEMAKER: KOA R[A; OUMEMAKERKATAMEI: RK73Z1JTTD; PMPRODUCTSTYPEG: DME-HD1-PC1; POWERRATING: 100m; QUADMODEL: RES_0; RESISTANCETOLER: X; SAVECOUNT: 0; SIZECODESMD: 1005; TIME: 13:58:25; UPDATEDATE: 2024/01/31; UPDATETIME: 13:58:25; VAL1: 0; VAL2: 63mW; VAL3: RK73Z1ETTP
R174 = R: CHIPSIZE: 1608; COMPONENTTYPE: 4; INSTANCENAME: cmp111; MAKER: KOA; NOTMOUNT: NOT MOUNT; SAVECOUNT: 0; SIZECODESMD: 1005; VAL1: 0; VAL2: 63mW; VAL3: RK73Z1ETTP
R175 = R: CHIPSIZE: 1608; COMPONENTTYPE: 4; INSTANCENAME: cmp115; MAKER: KOA; NOTMOUNT: NOT MOUNT; SAVECOUNT: 0; SIZECODESMD: 1005; VAL1: 0; VAL2: 63mW; VAL3: RK73Z1ETTP
R176 = R: CHIPSIZE: 1608; COMPONENTTYPE: 4; INSTANCENAME: cmp116; MAKER: KOA; NOTMOUNT: NOT MOUNT; SAVECOUNT: 0; SIZECODESMD: 1005; VAL1: 0; VAL2: 63mW; VAL3: RK73Z1ETTP
R177 = R: CHIPSIZE: 1608; COMPONENTTYPE: 4; INSTANCENAME: cmp117; MAKER: KOA; NOTMOUNT: NOT MOUNT; SAVECOUNT: 0; SIZECODESMD: 1005; VAL1: 0; VAL2: 63mW; VAL3: RK73Z1ETTP
R198 = R: CHIPSIZE: 1608; COMPONENTTYPE: 4; INSTANCENAME: cmp118; MAKER: KOA; NOTMOUNT: NOT MOUNT; SAVECOUNT: 0; SIZECODESMD: 1005; VAL1: 0; VAL2: 63mW; VAL3: RK73Z1ETTP
R227 = R: ADSMODELNAME: s_RC0402FR_071KL; ALLGREEN: 0:O[; CDMASTERCADCELG: KC0005; CHIPSIZE: 1608; COMPONENTTYPE: 4; FNAPPROVALRESUG: B:i(GREEN); FNCANCELLATIONG: 0:Žg—p‰Â; FNENVIRONMANTRG: 1:gpL(K§ÎÛO); FNLEADFREETHET1GT2GMCTH1: 2_2_N; GANSWERREV: 8; GCOUNT: 1; INSTANCENAME: cmp133; MAKER: KOA; MAXGCOUNT: 1; MOUNTINGFORMSMD: SMD; NOMINALRESISTAN: 1K; OUMECLASSIFICATION: \ÊÀpÅèïRí; OUMEMAKER: YGO ƒ„ƒQƒI; OUMEMAKERKATAMEI: RC0402FR-071KL; PMPRODUCTSTYPEG: HD1; POWERRATING: 63m; QUADMODEL: RES_1K; RESISTANCETOLER: F; SAVECOUNT: 0; SIZECODESMD: 1005; VAL1: 680(F); VAL2: 63mW; VAL3: RK73H1ERTTP6800F
R228 = R: ADSMODELNAME: s_RC0402FR_071KL; ALLGREEN: 0:O[; CDMASTERCADCELG: KC0005; CHIPSIZE: 1608; COMPONENTTYPE: 4; FNAPPROVALRESUG: B:i(GREEN); FNCANCELLATIONG: 0:Žg—p‰Â; FNENVIRONMANTRG: 1:gpL(K§ÎÛO); FNLEADFREETHET1GT2GMCTH1: 2_2_N; GANSWERREV: 8; GCOUNT: 1; INSTANCENAME: cmp154; MAKER: KOA; MAXGCOUNT: 1; MOUNTINGFORMSMD: SMD; NOMINALRESISTAN: 1K; OUMECLASSIFICATION: \ÊÀpÅèïRí; OUMEMAKER: YGO ƒ„ƒQƒI; OUMEMAKERKATAMEI: RC0402FR-071KL; PMPRODUCTSTYPEG: HD1; POWERRATING: 63m; QUADMODEL: RES_1K; RESISTANCETOLER: F; SAVECOUNT: 0; SIZECODESMD: 1005; VAL1: 680(F); VAL2: 63mW; VAL3: RK73H1ERTTP6800F
TP5 = TP: AUTHOR: sptcae13; COMP: PRT_44; COMPONENTTYPE: 4; DATE: 2024/01/31; INSTANCENAME: cmp119; MAKER: MAC8; TIME: 13:58:25; UPDATEDATE: 2024/01/31; UPDATETIME: 13:58:25; UPDATEUSER: sptcae13; VAL3: HK-2-S
TP6 = TP: AUTHOR: sptcae13; COMP: PRT_44; COMPONENTTYPE: 4; DATE: 2024/01/31; INSTANCENAME: cmp120; MAKER: MAC8; TIME: 13:58:25; UPDATEDATE: 2024/01/31; UPDATETIME: 13:58:25; UPDATEUSER: sptcae13; VAL3: HK-2-S
TP7 = TP: AUTHOR: sptcae13; COMP: PRT_44; COMPONENTTYPE: 4; DATE: 2024/01/31; INSTANCENAME: cmp121; MAKER: MAC8; TIME: 13:58:25; UPDATEDATE: 2024/01/31; UPDATETIME: 13:58:25; UPDATEUSER: sptcae13; VAL3: HK-2-S
TP8 = TP: AUTHOR: sptcae13; COMP: PRT_44; COMPONENTTYPE: 4; DATE: 2024/01/31; INSTANCENAME: cmp122; MAKER: MAC8; TIME: 13:58:25; UPDATEDATE: 2024/01/31; UPDATETIME: 13:58:25; UPDATEUSER: sptcae13; VAL3: HK-2-S
TP43 = TP: AUTHOR: sptcae13; COMP: PRT_49; COMPONENTTYPE: 4; DATE: 2024/01/31; INSTANCENAME: cmp124; MAKER: MAC8; TIME: 13:58:25; UPDATEDATE: 2024/01/31; UPDATETIME: 13:58:25; UPDATEUSER: sptcae13; VAL3: LC-22-S-WHITE
U?#6 = WAKU_DEF100: COMPONENTTYPE: 2; DATE: 2024/02/05; DESIGNED: TOSHIBA; DRAWINGNUMBER: RD240-SCHEMATIC-01; FUNCTION: PFC - Controller; INSTANCENAME: cmp168; PAGENUMBER: 3; REVISION: 01; SHEETNUMBER: 3/9; SHTSAVECOUNT: 47; TITLE: 1.6 kW Server Power Supply / (Upgraded); UPDATEDATE: 2024/02/07; UPDATETIME: 10:57:59; UPDATEUSER: t5459927

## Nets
VCC5R0_1: R117.2 ; also on sheet 3
VCC12R0_1: R116.1 R120.1 ; also on sheet 2 6 8 9
$BN000001: R90.2 R227.1
$BN000002: R2.2 R228.1
CSA: R170.1 ; also on sheet 8
CSB: R169.1 ; also on sheet 8
GDA: IC3.14 TP5.1 ; also on sheet 8
GDB: IC3.17 TP6.1 ; also on sheet 8
PFC_OUT: R92.2 ; also on sheet 2 6 8
PFC_VIN: R95.2 ; also on sheet 8
PN: C38.1 C39.1 C40.1 C42.1 C43.1 C45.1 C47.1 C48.1 C49.1 C50.1 C66.1 C67.1 C75.1 C76.1 C77.1 D49.A IC3.16 IC11.2 R2.1 R90.1 R93.1 R96.1 R98.1 R99.1 R100.1 R101.1 R102.1 R103.1 R104.1 R174.1 R175.1 R176.1 R198.1 TP43.1 ; also on sheet 2 3 6 8 9
SIG39: R89.2 R91.1
SIG40: R91.2 R92.1
SIG43: C45.2 C46.2 IC3.11
SIG44: C46.1 R99.2
SIG45: C43.2 C44.2 IC3.12
SIG46: C44.1 R98.2
SIG47: C40.2 C41.2 IC3.3
SIG48: C41.1 R93.2
SIG49: C39.2 IC3.4 R89.1 R227.2 TP8.1
SIG50: C49.2 IC3.18
SIG51: C50.2 IC3.1 R171.1
SIG52: IC3.19 R100.2 R198.2
SIG53: IC3.7 R101.2 R176.2
SIG54: IC3.6 R102.2 R175.2
SIG55: IC3.20 R103.2 R174.2
SIG56: IC3.2 R104.2
SIG60: R94.2 R95.1
SIG61: R1.2 R94.1
SIG62: C38.2 IC3.5 R1.1 R228.2 TP7.1
SIG86: C47.2 C48.2 D49.C IC3.15 R120.2
SIG185: C67.2 IC11.5 R117.1
SIG223: C66.2 IC11.1 IC11.3 R116.2
SIGN256: C77.2 IC3.10 R96.2 R97.1 R177.1
SIGN260: C76.2 IC3.9 R170.2
SIGN262: C75.2 IC3.8 R169.2
VREF_PFC: C42.2 IC3.13 R97.2 R171.2 R177.2

Not connected (* = marked no-connect by the designer): IC11 4

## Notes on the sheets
sheet 7
- for current
  measurement
- for current
  measurement
